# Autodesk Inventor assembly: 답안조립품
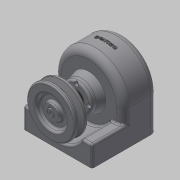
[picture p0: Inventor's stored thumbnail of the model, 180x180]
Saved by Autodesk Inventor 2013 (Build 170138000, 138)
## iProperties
Created: 2015-02
Part Number: 답안조립품
Document SubType Name: Assembly
Designer: Administrator
Author: Administrator
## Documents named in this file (10)
- C:\Users\Administrator\Desktop\450216V1019\답안조립품.iam
- C:\Users\Administrator\Desktop\450216V1019\본체.ipt
- C:\Users\Administrator\Desktop\450216V1019\축커버.ipt
- C:\Users\Administrator\Desktop\450216V1019\축.ipt
- C:\Users\Administrator\Desktop\450216V1019\베어링 6001.ipt
- C:\Users\Administrator\Desktop\450216V1019\키5x5.ipt
- C:\Users\Administrator\Desktop\450216V1019\키4x4.ipt
- C:\Users\Administrator\Desktop\450216V1019\오일실.ipt
- C:\Users\Administrator\Desktop\450216V1019\스퍼기어.ipt
- C:\Users\Administrator\Desktop\450216V1019\V-벨트풀리.ipt
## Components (1 placed, 1 different names)
1. V-벨트풀리:1 — 각도:2, 플러쉬:1
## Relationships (2: Angle 1, Flush 1)
- 각도:2 [Angle]: V-벨트풀리:1
- 플러쉬:1 [Flush]: V-벨트풀리:1
